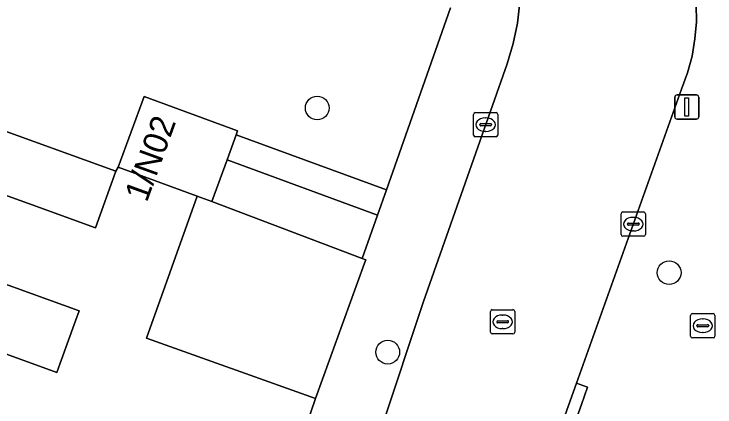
# Model space of a CAD drawing. Extents: x 161248 to 161848, y 384871 to 385383.
# Drawn here: x 161757.8 to 161786.65, y 385268.72 to 385284.89 of the extents above; entities that cross this region are included whole.
import ezdxf

# ---------------------------------------------------------------- set-up
doc = ezdxf.new("R2010")
doc.units = 0
for name, color, linetype in [('IMGEO_Boom', 7, 'Continuous'), ('IMGEO_Erf', 7, 'Continuous'), ('IMGEO_Groenvoorziening', 7, 'Continuous'), ('IMGEO_Kolk', 7, 'Continuous'), ('IMGEO_Lichtmast', 7, 'Continuous'), ('IMGEO_Muur', 7, 'Continuous'), ('IMGEO_Pand', 7, 'Continuous'), ('IMGEO_Pand_nummerreeks', 7, 'Continuous'), ('IMGEO_Rijbaan_lokaal_open', 7, 'Continuous'), ('IMGEO_Rioolput', 7, 'Continuous'), ('IMGEO_Voetpad_open', 7, 'Continuous')]:
    doc.layers.add(name, color=color, linetype=linetype)

msp = doc.modelspace()

# ---------------------------------------------------------------- linework, layer by layer
at = {"layer": 'IMGEO_Boom'}
for centre in [(161770.278, 385281.026), (161784.761, 385274.247), (161773.177, 385270.976)]:
    msp.add_circle(centre, 0.489, dxfattribs=at)
at = {"layer": 'IMGEO_Erf'}
for points in [[(161757.534, 385254.073), (161759.502, 385259.672), (161761.673, 385265.849), (161765.809, 385264.457), (161766.147, 385265.462), (161767.396, 385266.019), (161768.98, 385265.486), (161770.204, 385269.062), (161763.248, 385271.557), (161765.333, 385277.392), (161762.082, 385278.583), (161761.989, 385278.429), (161761.147, 385276.099), (161758.4, 385277.09), (161756.322, 385277.839)], [(161755.153, 385274.6), (161760.482, 385272.683), (161760.328, 385272.259), (161759.696, 385270.521), (161759.556, 385270.134), (161754.347, 385272.027)]]:
    msp.add_lwpolyline(points, dxfattribs=at)
at = {"layer": 'IMGEO_Groenvoorziening'}
msp.add_lwpolyline([(161751.356, 385282.266), (161761.989, 385278.429), (161762.082, 385278.583), (161763.148, 385281.494), (161767.001, 385280.083), (161766.942, 385279.921), (161773.123, 385277.656), (161775.757, 385285.151)], dxfattribs=at)
msp.add_lwpolyline([(161772.759, 385276.617), (161766.564, 385278.887), (161765.935, 385277.172), (161772.131, 385274.832)], close=True, dxfattribs=at)
at = {"layer": 'IMGEO_Kolk'}
for p, q in [((161776.783, 385280.838), (161777.635, 385280.838)), ((161776.708, 385279.912), (161776.708, 385280.764)), ((161777.196, 385280.618), (161777.221, 385280.618)), ((161777.709, 385280.764), (161777.709, 385279.912)), ((161776.967, 385280.332), (161776.967, 385280.344)), ((161777.405, 385280.295), (161777.007, 385280.295)), ((161777.01, 385280.381), (161777.408, 385280.381)), ((161777.451, 385280.344), (161777.451, 385280.332)), ((161777.219, 385280.058), (161777.194, 385280.058)), ((161777.635, 385279.838), (161776.783, 385279.838)), ((161782.783, 385275.819), (161782.783, 385276.671)), ((161782.858, 385276.745), (161783.71, 385276.745)), ((161783.271, 385276.525), (161783.296, 385276.525)), ((161783.784, 385276.671), (161783.784, 385275.819)), ((161783.042, 385276.239), (161783.042, 385276.251)), ((161783.48, 385276.202), (161783.082, 385276.202)), ((161783.085, 385276.288), (161783.483, 385276.288)), ((161783.526, 385276.251), (161783.526, 385276.239)), ((161783.294, 385275.965), (161783.269, 385275.965)), ((161783.71, 385275.745), (161782.858, 385275.745))]:
    msp.add_line(p, q, dxfattribs=at)
for points in [[(161776.783, 385280.838), (161777.635, 385280.838)], [(161776.708, 385279.912), (161776.708, 385280.764)], [(161777.709, 385280.764), (161777.709, 385279.912)], [(161777.635, 385279.838), (161776.783, 385279.838)], [(161782.783, 385275.819), (161782.783, 385276.671)], [(161782.858, 385276.745), (161783.71, 385276.745)], [(161783.784, 385276.671), (161783.784, 385275.819)], [(161783.71, 385275.745), (161782.858, 385275.745)]]:
    msp.add_lwpolyline(points, dxfattribs=at)
for centre, radius, start, end in [((161776.785, 385280.762), 0.0765, 91.552, 178.448), ((161776.785, 385280.762), 0.0765, 91.552, 178.448), ((161777.633, 385280.762), 0.0765, 1.552, 88.448), ((161777.633, 385280.762), 0.0765, 1.552, 88.448), ((161777.007, 385280.341), 0.0403, 85.8775, 175.7526), ((161777.004, 385280.331), 0.0366, 178.938, 274.7102), ((161777.408, 385280.338), 0.043, 264.8664, 352.4533), ((161777.412, 385280.343), 0.0386, 1.7309, 96.639), ((161776.785, 385279.914), 0.0765, 181.552, 268.448), ((161776.785, 385279.914), 0.0765, 181.552, 268.448), ((161777.633, 385279.914), 0.0765, 271.552, 358.448), ((161777.633, 385279.914), 0.0765, 271.552, 358.448), ((161782.86, 385276.669), 0.0765, 91.552, 178.448), ((161782.86, 385276.669), 0.0765, 91.552, 178.448), ((161783.708, 385276.669), 0.0765, 1.552, 88.448), ((161783.708, 385276.669), 0.0765, 1.552, 88.448), ((161783.082, 385276.248), 0.0403, 85.8775, 175.7526), ((161783.079, 385276.238), 0.0366, 178.938, 274.7102), ((161783.483, 385276.245), 0.043, 264.8664, 352.4533), ((161783.487, 385276.25), 0.0386, 1.7309, 96.639), ((161782.86, 385275.821), 0.0765, 181.552, 268.448), ((161782.86, 385275.821), 0.0765, 181.552, 268.448), ((161783.708, 385275.821), 0.0765, 271.552, 358.448), ((161783.708, 385275.821), 0.0765, 271.552, 358.448)]:
    msp.add_arc(centre, radius, start, end, dxfattribs=at)
for centre, major_axis, ratio, start_param, end_param in [((161777.195, 385280.338), (-0.387, 0.002), 0.722429, 4.712389, 7.853982), ((161777.22, 385280.338), (-0.39, 0.002), 0.717154, 1.570796, 4.712389), ((161783.27, 385276.245), (-0.387, 0.002), 0.722429, 4.712389, 7.853982), ((161783.295, 385276.245), (-0.39, 0.002), 0.717154, 1.570796, 4.712389)]:
    msp.add_ellipse(centre, major_axis=major_axis, ratio=ratio, start_param=start_param, end_param=end_param, dxfattribs=at)
at = {"layer": 'IMGEO_Lichtmast'}
for p, q in [((161784.99, 385280.665), (161784.99, 385281.465)), ((161784.99, 385281.465), (161784.99, 385280.665)), ((161785.09, 385281.565), (161785.88, 385281.565)), ((161785.88, 385281.565), (161785.09, 385281.565)), ((161785.98, 385281.465), (161785.98, 385280.665)), ((161785.98, 385280.665), (161785.98, 385281.465)), ((161785.88, 385280.565), (161785.09, 385280.565)), ((161785.09, 385280.565), (161785.88, 385280.565))]:
    msp.add_line(p, q, dxfattribs=at)
msp.add_lwpolyline([(161785.41, 385281.44), (161785.56, 385281.44), (161785.56, 385280.69), (161785.41, 385280.69), (161785.41, 385281.44)], dxfattribs=at)
for centre, start, end in [((161785.09, 385281.465), 90, 180), ((161785.09, 385281.465), 90, 180), ((161785.88, 385281.465), 0, 90), ((161785.88, 385281.465), 360, 90), ((161785.09, 385280.665), 180, 270), ((161785.09, 385280.665), 180, 270), ((161785.88, 385280.665), 270, 0), ((161785.88, 385280.665), 270, 0)]:
    msp.add_arc(centre, 0.1, start, end, dxfattribs=at)
at = {"layer": 'IMGEO_Muur'}
msp.add_lwpolyline([(161770.204, 385269.062), (161768.336, 385263.606)], dxfattribs=at)
at = {"layer": 'IMGEO_Pand'}
for points in [[(161761.989, 385278.429), (161751.356, 385282.266), (161750.75, 385280.404), (161748.827, 385281.089), (161747.497, 385277.354), (161748.363, 385277.042), (161755.153, 385274.6), (161756.322, 385277.839), (161758.4, 385277.09), (161761.147, 385276.099)], [(161766.564, 385278.887), (161766.942, 385279.921), (161767.001, 385280.083), (161763.148, 385281.494), (161762.082, 385278.583), (161765.333, 385277.392), (161765.935, 385277.172)], [(161765.935, 385277.172), (161765.333, 385277.392), (161763.248, 385271.557), (161770.204, 385269.062), (161772.221, 385274.64), (161772.271, 385274.779), (161772.131, 385274.832)], [(161755.153, 385274.6), (161748.363, 385277.042), (161747.393, 385274.322), (161746.929, 385274.487), (161745.84, 385271.43), (161753.17, 385268.791), (161754.347, 385272.027), (161759.556, 385270.134), (161759.696, 385270.521), (161760.328, 385272.259), (161760.482, 385272.683)]]:
    msp.add_lwpolyline(points, close=True, dxfattribs=at)
at = {"layer": 'IMGEO_Rijbaan_lokaal_open'}
for points in [[(161730.177, 385124.632), (161736.996, 385144.544), (161740.956, 385156.108), (161742.83, 385161.454), (161757.564, 385203.488), (161757.857, 385204.325), (161760.395, 385211.566), (161765.249, 385225.382), (161768.452, 385234.5), (161773.897, 385250), (161777.978, 385261.406), (161780.943, 385269.693), (161785.276, 385281.802), (161785.52, 385282.473), (161785.703, 385283.163), (161785.823, 385283.866), (161785.88, 385284.578), (161785.874, 385285.292), (161785.803, 385286.002), (161785.673, 385286.689), (161785.312, 385289.733), (161785.296, 385289.929), (161784.343, 385297.154)], [(161778.618, 385285.376), (161778.519, 385284.519), (161778.344, 385283.674), (161778.094, 385282.848), (161774.649, 385273.059), (161771.25, 385262.826)]]:
    msp.add_lwpolyline(points, dxfattribs=at)
at = {"layer": 'IMGEO_Rioolput'}
for p, q in [((161777.481, 385272.724), (161778.333, 385272.724)), ((161777.406, 385271.798), (161777.406, 385272.65)), ((161777.894, 385272.504), (161777.919, 385272.504)), ((161778.407, 385272.65), (161778.407, 385271.798)), ((161785.646, 385271.636), (161785.646, 385272.488)), ((161785.721, 385272.562), (161786.573, 385272.562)), ((161786.647, 385272.488), (161786.647, 385271.636)), ((161777.665, 385272.218), (161777.665, 385272.23)), ((161778.103, 385272.181), (161777.705, 385272.181)), ((161777.708, 385272.267), (161778.106, 385272.267)), ((161778.149, 385272.23), (161778.149, 385272.218)), ((161786.134, 385272.342), (161786.159, 385272.342)), ((161777.917, 385271.944), (161777.892, 385271.944)), ((161785.905, 385272.056), (161785.905, 385272.068)), ((161786.343, 385272.019), (161785.945, 385272.019)), ((161785.948, 385272.105), (161786.346, 385272.105)), ((161786.389, 385272.068), (161786.389, 385272.056)), ((161778.333, 385271.724), (161777.481, 385271.724)), ((161786.157, 385271.782), (161786.132, 385271.782)), ((161786.573, 385271.562), (161785.721, 385271.562))]:
    msp.add_line(p, q, dxfattribs=at)
for points in [[(161777.481, 385272.724), (161778.333, 385272.724)], [(161777.406, 385271.798), (161777.406, 385272.65)], [(161778.407, 385272.65), (161778.407, 385271.798)], [(161785.646, 385271.636), (161785.646, 385272.488)], [(161785.721, 385272.562), (161786.573, 385272.562)], [(161786.647, 385272.488), (161786.647, 385271.636)], [(161778.333, 385271.724), (161777.481, 385271.724)], [(161786.573, 385271.562), (161785.721, 385271.562)]]:
    msp.add_lwpolyline(points, dxfattribs=at)
for centre, radius, start, end in [((161777.483, 385272.648), 0.0765, 91.552, 178.448), ((161777.483, 385272.648), 0.0765, 91.552, 178.448), ((161778.331, 385272.648), 0.0765, 1.552, 88.448), ((161778.331, 385272.648), 0.0765, 1.552, 88.448), ((161785.723, 385272.486), 0.0765, 91.552, 178.448), ((161785.723, 385272.486), 0.0765, 91.552, 178.448), ((161786.571, 385272.486), 0.0765, 1.552, 88.448), ((161786.571, 385272.486), 0.0765, 1.552, 88.448), ((161777.705, 385272.227), 0.0403, 85.8775, 175.7526), ((161777.702, 385272.217), 0.0366, 178.938, 274.7102), ((161778.106, 385272.224), 0.043, 264.8664, 352.4533), ((161778.11, 385272.229), 0.0386, 1.7309, 96.639), ((161785.945, 385272.065), 0.0403, 85.8775, 175.7526), ((161785.942, 385272.055), 0.0366, 178.938, 274.7102), ((161786.346, 385272.062), 0.043, 264.8664, 352.4533), ((161786.35, 385272.067), 0.0386, 1.7309, 96.639), ((161777.483, 385271.8), 0.0765, 181.552, 268.448), ((161777.483, 385271.8), 0.0765, 181.552, 268.448), ((161778.331, 385271.8), 0.0765, 271.552, 358.448), ((161778.331, 385271.8), 0.0765, 271.552, 358.448), ((161785.723, 385271.638), 0.0765, 181.552, 268.448), ((161785.723, 385271.638), 0.0765, 181.552, 268.448), ((161786.571, 385271.638), 0.0765, 271.552, 358.448), ((161786.571, 385271.638), 0.0765, 271.552, 358.448)]:
    msp.add_arc(centre, radius, start, end, dxfattribs=at)
for centre, major_axis, ratio, start_param, end_param in [((161777.893, 385272.224), (-0.387, 0.002), 0.722429, 4.712389, 7.853982), ((161777.918, 385272.224), (-0.39, 0.002), 0.717154, 1.570796, 4.712389), ((161786.133, 385272.062), (-0.387, 0.002), 0.722429, 4.712389, 7.853982), ((161786.158, 385272.062), (-0.39, 0.002), 0.717154, 1.570796, 4.712389)]:
    msp.add_ellipse(centre, major_axis=major_axis, ratio=ratio, start_param=start_param, end_param=end_param, dxfattribs=at)
at = {"layer": 'IMGEO_Voetpad_open'}
for points in [[(161785.296, 385289.929), (161785.312, 385289.733), (161785.673, 385286.689), (161785.803, 385286.002), (161785.874, 385285.292), (161785.88, 385284.578), (161785.823, 385283.866), (161785.703, 385283.163), (161785.52, 385282.473), (161785.276, 385281.802), (161780.943, 385269.693), (161781.403, 385269.529), (161781.152, 385268.827), (161778.441, 385261.241), (161777.978, 385261.406), (161773.897, 385250), (161768.452, 385234.5), (161765.249, 385225.382), (161760.395, 385211.566), (161757.857, 385204.325)], [(161775.757, 385285.151), (161773.123, 385277.656), (161772.759, 385276.617), (161772.131, 385274.832), (161772.271, 385274.779), (161772.221, 385274.64), (161770.204, 385269.062), (161768.98, 385265.486)], [(161771.25, 385262.826), (161774.649, 385273.059), (161778.094, 385282.848), (161778.344, 385283.674), (161778.519, 385284.519), (161778.618, 385285.376)]]:
    msp.add_lwpolyline(points, dxfattribs=at)
for points in [[(161766.564, 385278.887), (161772.759, 385276.617), (161773.123, 385277.656), (161766.942, 385279.921)], [(161777.978, 385261.406), (161778.441, 385261.241), (161781.152, 385268.827), (161781.403, 385269.529), (161780.943, 385269.693)]]:
    msp.add_lwpolyline(points, close=True, dxfattribs=at)

# ---------------------------------------------------------------- texts
at = {"layer": 'IMGEO_Pand_nummerreeks'}
msp.add_text('1/N02', height=1, rotation=70.0963, dxfattribs=at).set_placement((161763.263, 385277.109))

doc.saveas('drawing.dxf')
